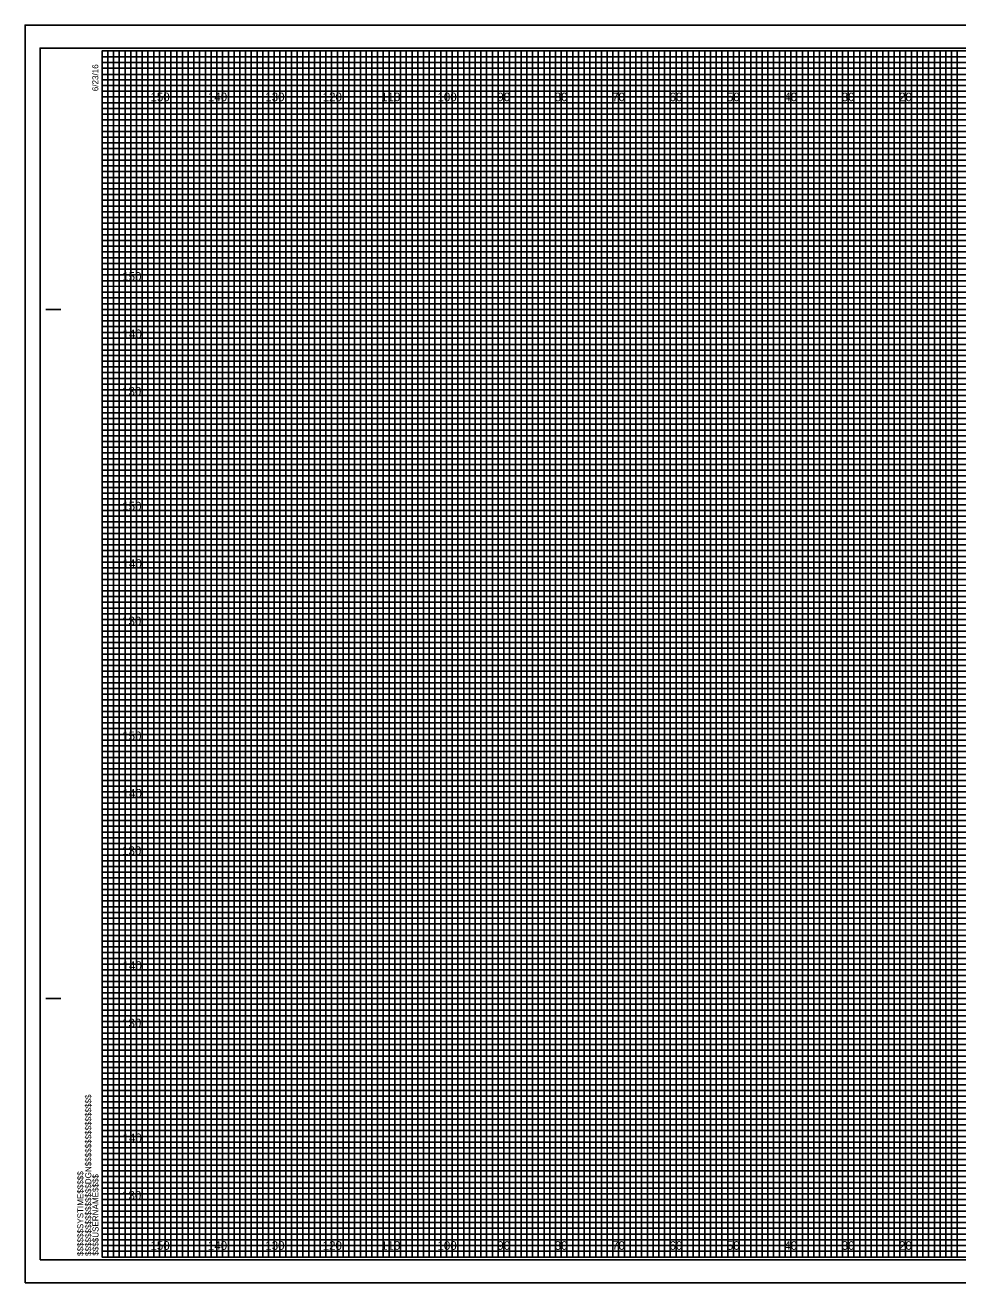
# Model space of a CAD drawing. Extents: x -13 to 323, y -5 to 3294.
# Drawn here: x -13.4 to 149.1, y 1975.5 to 2194.5 of the extents above; entities that cross this region are included whole.
import ezdxf

# ---------------------------------------------------------------- set-up
doc = ezdxf.new("R2010")
doc.units = 0
for name, color, linetype in [('Prop XS Elevation Labels', 7, 'Continuous'), ('Prop XS Offset Labels', 7, 'Continuous'), ('Sheet Cross Section CELL', 7, 'Continuous'), ('Sheet Cross Section Grid Major CELL', 7, 'Continuous'), ('Sheet Cross Section Grid Middle CELL', 7, 'Continuous'), ('Sheet Cross Section Grid Minor 1 CELL', 7, 'Continuous'), ('Sheet Cross Section Grid Minor 2 CELL', 7, 'Continuous'), ('Sheet Cutting Line CELL', 7, 'Continuous'), ('Sheet DOT Grid CELL', 7, 'Continuous'), ('Sheet Plot Border Inside CELL', 7, 'Continuous'), ('Sheet Plot Border Outside CELL', 7, 'Continuous')]:
    doc.layers.add(name, color=color, linetype=linetype)

msp = doc.modelspace()

# ---------------------------------------------------------------- linework, layer by layer
at = {"layer": 'Sheet Cross Section CELL'}
for p, q in [((-9.8, 2145), (-7.3, 2145)), ((-9.7, 2145), (-7.2, 2145)), ((-9.8, 2025), (-7.3, 2025)), ((-9.7, 2025), (-7.2, 2025)), ((0, 1980), (0, 1980)), ((0, 1980), (0, 1980)), ((0, 1980), (0, 1980)), ((0, 1980), (0, 1980)), ((0, 1980), (0, 1980)), ((0, 1980), (0, 1980)), ((0, 1980), (0, 1980))]:
    msp.add_line(p, q, dxfattribs=at)
msp.add_lwpolyline([(320, 2190), (0, 2190), (0, 1980), (320, 1980)], close=True, dxfattribs=at)
at = {"layer": 'Sheet Cross Section Grid Major CELL'}
for p, q in [((10, 2190), (0, 2190)), ((10, 1980), (10, 2190)), ((30, 2190), (20, 2190)), ((20, 2190), (20, 1980)), ((30, 1980), (30, 2190)), ((50, 2190), (40, 2190)), ((40, 2190), (40, 1980)), ((50, 1980), (50, 2190)), ((70, 2190), (60, 2190)), ((60, 2190), (60, 1980)), ((70, 1980), (70, 2190)), ((90, 2190), (80, 2190)), ((80, 2190), (80, 1980)), ((90, 1980), (90, 2190)), ((110, 2190), (100, 2190)), ((100, 2190), (100, 1980)), ((110, 1980), (110, 2190)), ((130, 2190), (120, 2190)), ((120, 2190), (120, 1980)), ((130, 1980), (130, 2190)), ((150, 2190), (140, 2190)), ((140, 2190), (140, 1980)), ((20, 1980), (10, 1980)), ((40, 1980), (30, 1980)), ((60, 1980), (50, 1980)), ((80, 1980), (70, 1980)), ((100, 1980), (90, 1980)), ((120, 1980), (110, 1980)), ((140, 1980), (130, 1980))]:
    msp.add_line(p, q, dxfattribs=at)
for points in [[(0, 2180), (320, 2180), (320, 2170), (0, 2170)], [(0, 2160), (320, 2160), (320, 2150), (0, 2150)], [(0, 2140), (320, 2140), (320, 2130), (0, 2130)], [(0, 2120), (320, 2120), (320, 2110), (0, 2110)], [(0, 2100), (320, 2100), (320, 2090), (0, 2090)], [(0, 2080), (320, 2080), (320, 2070), (0, 2070)], [(0, 2060), (320, 2060), (320, 2050), (0, 2050)], [(0, 2040), (320, 2040), (320, 2030), (0, 2030)], [(0, 2020), (320, 2020), (320, 2010), (0, 2010)], [(0, 2000), (320, 2000), (320, 1990), (0, 1990)]]:
    msp.add_lwpolyline(points, dxfattribs=at)
at = {"layer": 'Sheet Cross Section Grid Middle CELL'}
for points in [[(0, 2190), (5, 2190), (5, 1980), (15, 1980), (15, 2190), (25, 2190), (25, 1980), (35, 1980), (35, 2190), (45, 2190), (45, 1980), (55, 1980), (55, 2190), (65, 2190), (65, 1980), (75, 1980), (75, 2190), (85, 2190), (85, 1980), (95, 1980), (95, 2190), (105, 2190), (105, 1980), (115, 1980), (115, 2190), (125, 2190), (125, 1980), (135, 1980), (135, 2190), (145, 2190), (145, 1980), (155, 1980)], [(0, 2185), (275, 2185)], [(0, 2165), (320, 2165), (320, 2175), (0, 2175)], [(0, 2145), (320, 2145), (320, 2155), (0, 2155)], [(0, 2125), (320, 2125), (320, 2135), (0, 2135)], [(0, 2105), (320, 2105), (320, 2115), (0, 2115)], [(0, 2085), (320, 2085), (320, 2095), (0, 2095)], [(0, 2065), (320, 2065), (320, 2075), (0, 2075)], [(0, 2045), (320, 2045), (320, 2055), (0, 2055)], [(0, 2025), (320, 2025), (320, 2035), (0, 2035)], [(0, 2005), (320, 2005), (320, 2015), (0, 2015)], [(0, 1985), (320, 1985), (320, 1995), (0, 1995)]]:
    msp.add_lwpolyline(points, dxfattribs=at)
at = {"layer": 'Sheet Cross Section Grid Minor 1 CELL'}
for p, q in [((0, 2189), (260, 2189)), ((260, 2187.98), (0, 2187.98)), ((0, 2187.98), (0, 2187)), ((0, 2187), (260, 2187)), ((260, 2185.89), (0, 2185.89)), ((0, 2185.89), (0, 2184)), ((0, 2184), (320, 2184))]:
    msp.add_line(p, q, dxfattribs=at)
for points in [[(0, 2183), (270, 2183), (320, 2183), (320, 2182), (0, 2182)], [(0, 2181), (320, 2181), (320, 2179), (0, 2179)], [(0, 2178), (320, 2178), (320, 2177), (0, 2176.98)], [(0, 2176), (320, 2176), (320, 2174), (0, 2174)], [(0, 2173), (320, 2173), (320, 2172), (0, 2172)], [(0, 2171), (320, 2171), (320, 2169), (0, 2169)], [(0, 2168), (320, 2168), (320, 2167), (0, 2167)], [(0, 2166), (320, 2166), (320, 2164), (0, 2164)], [(0, 2163), (320, 2163), (320, 2162), (0, 2162)], [(0, 2161), (320, 2161), (320, 2159), (0, 2159)], [(0, 2158), (320, 2158), (320, 2157), (0, 2157)], [(0, 2156), (320, 2156), (320, 2153.95), (320, 2153), (320, 2152), (0, 2152)], [(0, 2154), (320, 2154), (320, 2153), (0, 2153)], [(0, 2151), (320, 2151), (320, 2149), (0, 2149.03)], [(0, 2149.03), (320, 2149), (320, 2148), (0, 2148)], [(0, 2147), (320, 2147), (320, 2146), (0, 2146)], [(0, 2144), (320, 2144), (320, 2143), (0, 2143)], [(0, 2142), (320, 2142), (320, 2141), (0, 2141)], [(-0.07, 2138.89), (320, 2138.89), (320, 2137.88), (-0.07, 2137.88)], [(0, 2137), (320, 2137), (320, 2136), (0, 2136)], [(0, 2134), (320, 2134), (320, 2133), (0, 2133)], [(0, 2132), (320, 2132), (320, 2131), (0, 2131)], [(0, 2129), (320, 2129), (320, 2128), (0, 2128)], [(0, 2127), (320, 2127), (320, 2126), (0, 2126)], [(0, 2124), (320, 2124), (320, 2123), (0, 2123)], [(0, 2122), (320, 2122), (320, 2121), (0, 2121)], [(0, 2119), (320, 2119), (319.99, 2117.98), (0, 2118)], [(0, 2117), (320, 2117), (320, 2116), (0, 2116)], [(0, 2114), (320, 2114), (320, 2113), (0, 2113)], [(0, 2112), (320, 2112), (320, 2111), (0, 2111)], [(0, 2109), (320, 2109), (320, 2108), (0, 2108)], [(0, 2107), (320, 2107), (320, 2106), (0, 2106)], [(0, 2104), (320, 2104), (320, 2103), (0, 2103)], [(0, 2102), (320, 2102), (320, 2101), (0, 2101)], [(0, 2099), (320, 2099), (320, 2098), (0, 2098)], [(0, 2096.99), (320.07, 2096.91), (320, 2096), (0, 2096)], [(0, 2094), (320, 2094), (320, 2093), (0, 2093)], [(0, 2092), (320, 2092), (320, 2091), (0, 2091)], [(0, 2089), (320, 2089), (320, 2088), (0, 2088)], [(0, 2087), (320, 2087), (320, 2086), (0, 2086)], [(0, 2084), (320, 2084), (320, 2083), (0, 2083)], [(0, 2082), (320, 2082), (320, 2081), (0, 2081)], [(0, 2079), (320, 2079), (320, 2078), (0, 2078)], [(0, 2077), (320, 2077), (320, 2076), (0, 2076)], [(0, 2074), (320, 2074), (320, 2073), (0, 2073)], [(0, 2072), (320, 2072), (320, 2071), (0, 2071)], [(0, 2069), (320, 2069), (320, 2068), (0, 2068)], [(0, 2067), (320, 2067), (320, 2066), (0, 2066)], [(0, 2064), (320, 2064), (320, 2063), (0, 2063)], [(0, 2062), (320, 2062), (320, 2061), (0, 2061)], [(0, 2059), (320, 2059), (319.99, 2057.98), (0, 2058)], [(0, 2057), (320, 2057), (320, 2056), (0, 2056)], [(0, 2054), (320, 2054), (320, 2053), (0, 2053)], [(0, 2052), (320, 2052), (320, 2051), (0, 2051)], [(0, 2049), (320, 2049), (320, 2048), (0, 2048)], [(0, 2047), (320, 2047), (320, 2046), (0, 2046)], [(0, 2044), (320, 2044), (320, 2043), (0, 2043)], [(0, 2042), (320, 2042), (320, 2041), (0, 2041)], [(0, 2039), (320, 2039), (320, 2038), (0, 2038)], [(0, 2036.99), (320.07, 2036.91), (320, 2036), (0, 2036)], [(0, 2034), (320, 2034), (320, 2033), (0, 2033)], [(0, 2032), (320, 2032), (320, 2031), (0, 2031)], [(0, 2029), (320, 2029), (320, 2028), (0, 2028)], [(0, 2027), (320, 2027), (320, 2026), (0, 2026)], [(0, 2024), (320, 2024), (320, 2023), (0, 2023)], [(0, 2022), (320, 2022), (320, 2021), (0, 2021)], [(0, 2019), (320, 2019), (320, 2018), (0, 2018)], [(0, 2017), (320, 2017), (320, 2016), (0, 2016)], [(0, 2014), (320, 2014), (320, 2013), (0, 2013)], [(0, 2012), (320, 2012), (320, 2011), (0, 2011)], [(0, 2009), (320, 2009), (320, 2008), (0, 2008)], [(0, 2007), (320, 2007), (320, 2006), (0, 2006)], [(0, 2004), (320, 2004), (320, 2003), (0, 2003)], [(0, 2002), (320, 2002), (320, 2001), (0, 2001)], [(0, 1999), (320, 1999), (320, 1998), (0, 1998)], [(0, 1997), (320, 1997), (320, 1996), (0, 1996)], [(0, 1994), (320, 1994), (320, 1993), (0, 1993)], [(0, 1992), (320, 1992), (320, 1991), (0, 1991)], [(0, 1989), (320, 1989), (320, 1988), (0, 1988)], [(0, 1987), (320, 1987), (320, 1986), (0, 1986)], [(0, 1984), (320, 1984), (320, 1983), (0, 1983)], [(0, 1982), (320, 1982), (320, 1981), (0, 1981)]]:
    msp.add_lwpolyline(points, dxfattribs=at)
at = {"layer": 'Sheet Cross Section Grid Minor 2 CELL'}
for points in [[(0, 1980), (1, 1980), (1, 2190), (2, 2190), (2, 1980)], [(2, 1980), (3, 1980), (3, 2190), (4, 2190), (4, 1980)], [(5, 1980), (6, 1980), (6, 2190), (7, 2190), (7, 1980)], [(7, 1980), (8, 1980), (8, 2190), (9, 2190), (9, 1980)], [(10, 1980), (11, 1980), (11, 2190), (12, 2190), (12, 1980)], [(12, 1980), (13, 1980), (13, 2190), (14, 2190), (14, 1980)], [(15, 1980), (16, 1980), (16, 2190), (17, 2190), (17, 1980)], [(17, 1980), (18, 1980), (18, 2190), (19, 2190), (19, 1980)], [(20, 1980), (21, 1980), (21, 2190), (22, 2190), (22, 1980)], [(22, 1980), (23, 1980), (23, 2190), (24, 2190), (24, 1980)], [(25, 1980), (26, 1980), (26, 2190), (27, 2190), (27, 1980)], [(27, 1980), (28, 1980), (28, 2190), (29, 2190), (29, 1980)], [(30, 1980), (31, 1980), (31, 2190), (32, 2190), (32, 1980)], [(32, 1980), (33, 1980), (33, 2190), (34, 2190), (34, 1980)], [(35, 1980), (36, 1980), (36, 2190), (37, 2190), (37, 1980)], [(37, 1980), (38, 1980), (38, 2190), (39, 2190), (39, 1980)], [(40, 1980), (41, 1980), (41, 2190), (42, 2190), (42, 1980)], [(42, 1980), (43, 1980), (43, 2190), (44, 2190), (44, 1980)], [(45, 1980), (46, 1980), (46, 2190), (47, 2190), (47, 1980)], [(47, 1980), (48, 1980), (48, 2190), (49, 2190), (49, 1980)], [(50, 1980), (51, 1980), (51, 2190), (52, 2190), (52, 1980)], [(52, 1980), (53, 1980), (53, 2190), (54, 2190), (54, 1980)], [(55, 1980), (56, 1980), (56, 2190), (57, 2190), (57, 1980)], [(57, 1980), (58, 1980), (58, 2190), (59, 2190), (59, 1980)], [(60, 1980), (61, 1980), (61, 2190), (62, 2190), (62, 1980)], [(62, 1980), (63, 1980), (63, 2190), (64, 2190), (64, 1980)], [(65, 1980), (66, 1980), (66, 2190), (67, 2190), (67, 1980)], [(67, 1980), (68, 1980), (68, 2190), (69, 2190), (69, 1980)], [(70, 1980), (71, 1980), (71, 2190), (72, 2190), (72, 1980)], [(72, 1980), (73, 1980), (73, 2190), (74, 2190), (74, 1980)], [(75, 1980), (76, 1980), (76, 2190), (77, 2190), (77, 1980)], [(77, 1980), (78, 1980), (78, 2190), (79, 2190), (79, 1980)], [(80, 1980), (81, 1980), (81, 2190), (82, 2190), (82, 1980)], [(82, 1980), (83, 1980), (83, 2190), (84, 2190), (84, 1980)], [(85, 1980), (86, 1980), (86, 2190), (87, 2190), (87, 1980)], [(87, 1980), (88, 1980), (88, 2190), (89, 2190), (89, 1980)], [(90, 1980), (91, 1980), (91, 2190), (92, 2190), (92, 1980)], [(92, 1980), (93, 1980), (93, 2190), (94, 2190), (94, 1980)], [(95, 1980), (96, 1980), (96, 2190), (97, 2190), (97, 1980)], [(97, 1980), (98, 1980), (98, 2190), (99, 2190), (99, 1980)], [(100, 1980), (101, 1980), (101, 2190), (102, 2190), (102, 1980)], [(102, 1980), (103, 1980), (103, 2190), (104, 2190), (104, 1980)], [(105, 1980), (106, 1980), (106, 2190), (107, 2190), (107, 1980)], [(107, 1980), (108, 1980), (108, 2190), (109, 2190), (109, 1980)], [(110, 1980), (111, 1980), (111, 2190), (112, 2190), (112, 1980)], [(112, 1980), (113, 1980), (113, 2190), (114, 2190), (114, 1980)], [(115, 1980), (116, 1980), (116, 2190), (117, 2190), (117, 1980)], [(117, 1980), (118, 1980), (118, 2190), (119, 2190), (119, 1980)], [(120, 1980), (121, 1980), (121, 2190), (122, 2190), (122, 1980)], [(122, 1980), (123, 1980), (123, 2190), (124, 2190), (124, 1980)], [(125, 1980), (126, 1980), (126, 2190), (127, 2190), (127, 1980)], [(127, 1980), (128, 1980), (128, 2190), (129, 2190), (129, 1980)], [(130, 1980), (131, 1980), (131, 2190), (132, 2190), (132, 1980)], [(132, 1980), (133, 1980), (133, 2190), (134, 2190), (134, 1980)], [(135, 1980), (136, 1980), (136, 2190), (137, 2190), (137, 1980)], [(137, 1980), (138, 1980), (138, 2190), (139, 2190), (139, 1980)], [(140, 1980), (141, 1980), (141, 2190), (142, 2190), (142, 1980)], [(142, 1980), (143, 1980), (143, 2190), (144, 2190), (144, 1980)], [(145, 1980), (146, 1980), (146, 2190), (147, 2190), (147, 1980)], [(147, 1980), (148, 1980), (148, 2190), (149, 2190), (149, 1980)]]:
    msp.add_lwpolyline(points, dxfattribs=at)
at = {"layer": 'Sheet Cutting Line CELL'}
for p, q in [((323.3, 2194.5), (-13.4, 2194.5)), ((-13.4, 2194.5), (-13.4, 1975.5)), ((-13.4, 1975.5), (323.3, 1975.5))]:
    msp.add_line(p, q, dxfattribs=at)
at = {"layer": 'Sheet DOT Grid CELL'}
for p, q in [((10, 1980), (10, 2190)), ((20, 1980), (20, 2190)), ((30, 1980), (30, 2190)), ((40, 1980), (40, 2190)), ((50, 1980), (50, 2190)), ((60, 1980), (60, 2190)), ((70, 1980), (70, 2190)), ((80, 1980), (80, 2190)), ((90, 1980), (90, 2190)), ((100, 1980), (100, 2190)), ((110, 1980), (110, 2190)), ((120, 1980), (120, 2190)), ((130, 1980), (130, 2190)), ((140, 1980), (140, 2190)), ((0, 2180), (320, 2180)), ((0, 2170), (320, 2170)), ((0, 2160), (320, 2160)), ((0, 2150), (320, 2150)), ((0, 2140), (320, 2140)), ((0, 2130), (320, 2130)), ((0, 2120), (320, 2120)), ((0, 2110), (320, 2110)), ((0, 2100), (320, 2100)), ((0, 2090), (320, 2090)), ((0, 2080), (320, 2080)), ((0, 2070), (320, 2070)), ((0, 2060), (320, 2060)), ((0, 2050), (320, 2050)), ((0, 2040), (320, 2040)), ((0, 2030), (320, 2030)), ((0, 2020), (320, 2020)), ((0, 2010), (320, 2010)), ((0, 2000), (320, 2000)), ((0, 1990), (320, 1990))]:
    msp.add_line(p, q, dxfattribs=at)
at = {"layer": 'Sheet Plot Border Inside CELL'}
msp.add_lwpolyline([(-10.8, 1979.5), (322.4, 1979.5), (322.4, 2190.5), (-10.8, 2190.5)], close=True, dxfattribs=at)
at = {"layer": 'Sheet Plot Border Outside CELL'}
msp.add_lwpolyline([(-13.4, 1975.5), (323.3, 1975.5), (323.3, 2194.5), (-13.4, 2194.5)], close=True, dxfattribs=at)

# ---------------------------------------------------------------- texts
at = {"layer": 'Prop XS Elevation Labels'}
for s, p in [('150', (3.52, 2150)), ('140', (3.57, 2140)), ('130', (3.49, 2130)), ('150', (3.52, 2110)), ('140', (3.57, 2100)), ('130', (3.49, 2090)), ('150', (3.52, 2070)), ('140', (3.57, 2060)), ('130', (3.49, 2050)), ('140', (3.57, 2030)), ('130', (3.49, 2020)), ('140', (3.57, 2000)), ('130', (3.49, 1990))]:
    msp.add_text(s, height=1.5, dxfattribs=at).set_placement(p)
at = {"layer": 'Prop XS Offset Labels'}
for s, p in [('150', (8.44, 2181.25)), ('140', (18.44, 2181.25)), ('130', (28.44, 2181.25)), ('120', (38.44, 2181.25)), ('110', (48.62, 2181.25)), ('100', (58.44, 2181.25)), ('90', (68.86, 2181.25)), ('80', (78.86, 2181.25)), ('70', (88.86, 2181.25)), ('60', (98.86, 2181.25)), ('50', (108.86, 2181.25)), ('40', (118.86, 2181.25)), ('30', (128.86, 2181.25)), ('20', (138.86, 2181.25)), ('150', (8.44, 1981.25)), ('140', (18.44, 1981.25)), ('130', (28.44, 1981.25)), ('120', (38.44, 1981.25)), ('110', (48.62, 1981.25)), ('100', (58.44, 1981.25)), ('90', (68.86, 1981.25)), ('80', (78.86, 1981.25)), ('70', (88.86, 1981.25)), ('60', (98.86, 1981.25)), ('50', (108.86, 1981.25)), ('40', (118.86, 1981.25)), ('30', (128.86, 1981.25)), ('20', (138.86, 1981.25))]:
    msp.add_text(s, height=1.5, dxfattribs=at).set_placement(p)
at = {"layer": 'Sheet Cross Section CELL'}
for s, p in [('6/23/16', (-0.65, 2183)), ('$$$$$$$$$$$$$$$$DGN$$$$$$$$$$$$$$$$', (-1.88, 1980.18)), ('$$$$$$SYSTIME$$$$$', (-3.26, 1980.18)), ('$$$$USERNAME$$$$', (-0.62, 1980.23))]:
    msp.add_text(s, height=1.05, rotation=90, dxfattribs=at).set_placement(p)

doc.saveas('drawing.dxf')
